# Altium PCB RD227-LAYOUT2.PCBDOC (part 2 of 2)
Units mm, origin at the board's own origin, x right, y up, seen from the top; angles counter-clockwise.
Board outline 90 x 40 mm, 4 copper layers (TOP, Mid-Layer 1, Mid-Layer 2, BOTTOM), stack 0.711 mm thick; 157 components, 70 nets, 404 pads, 437 vias.
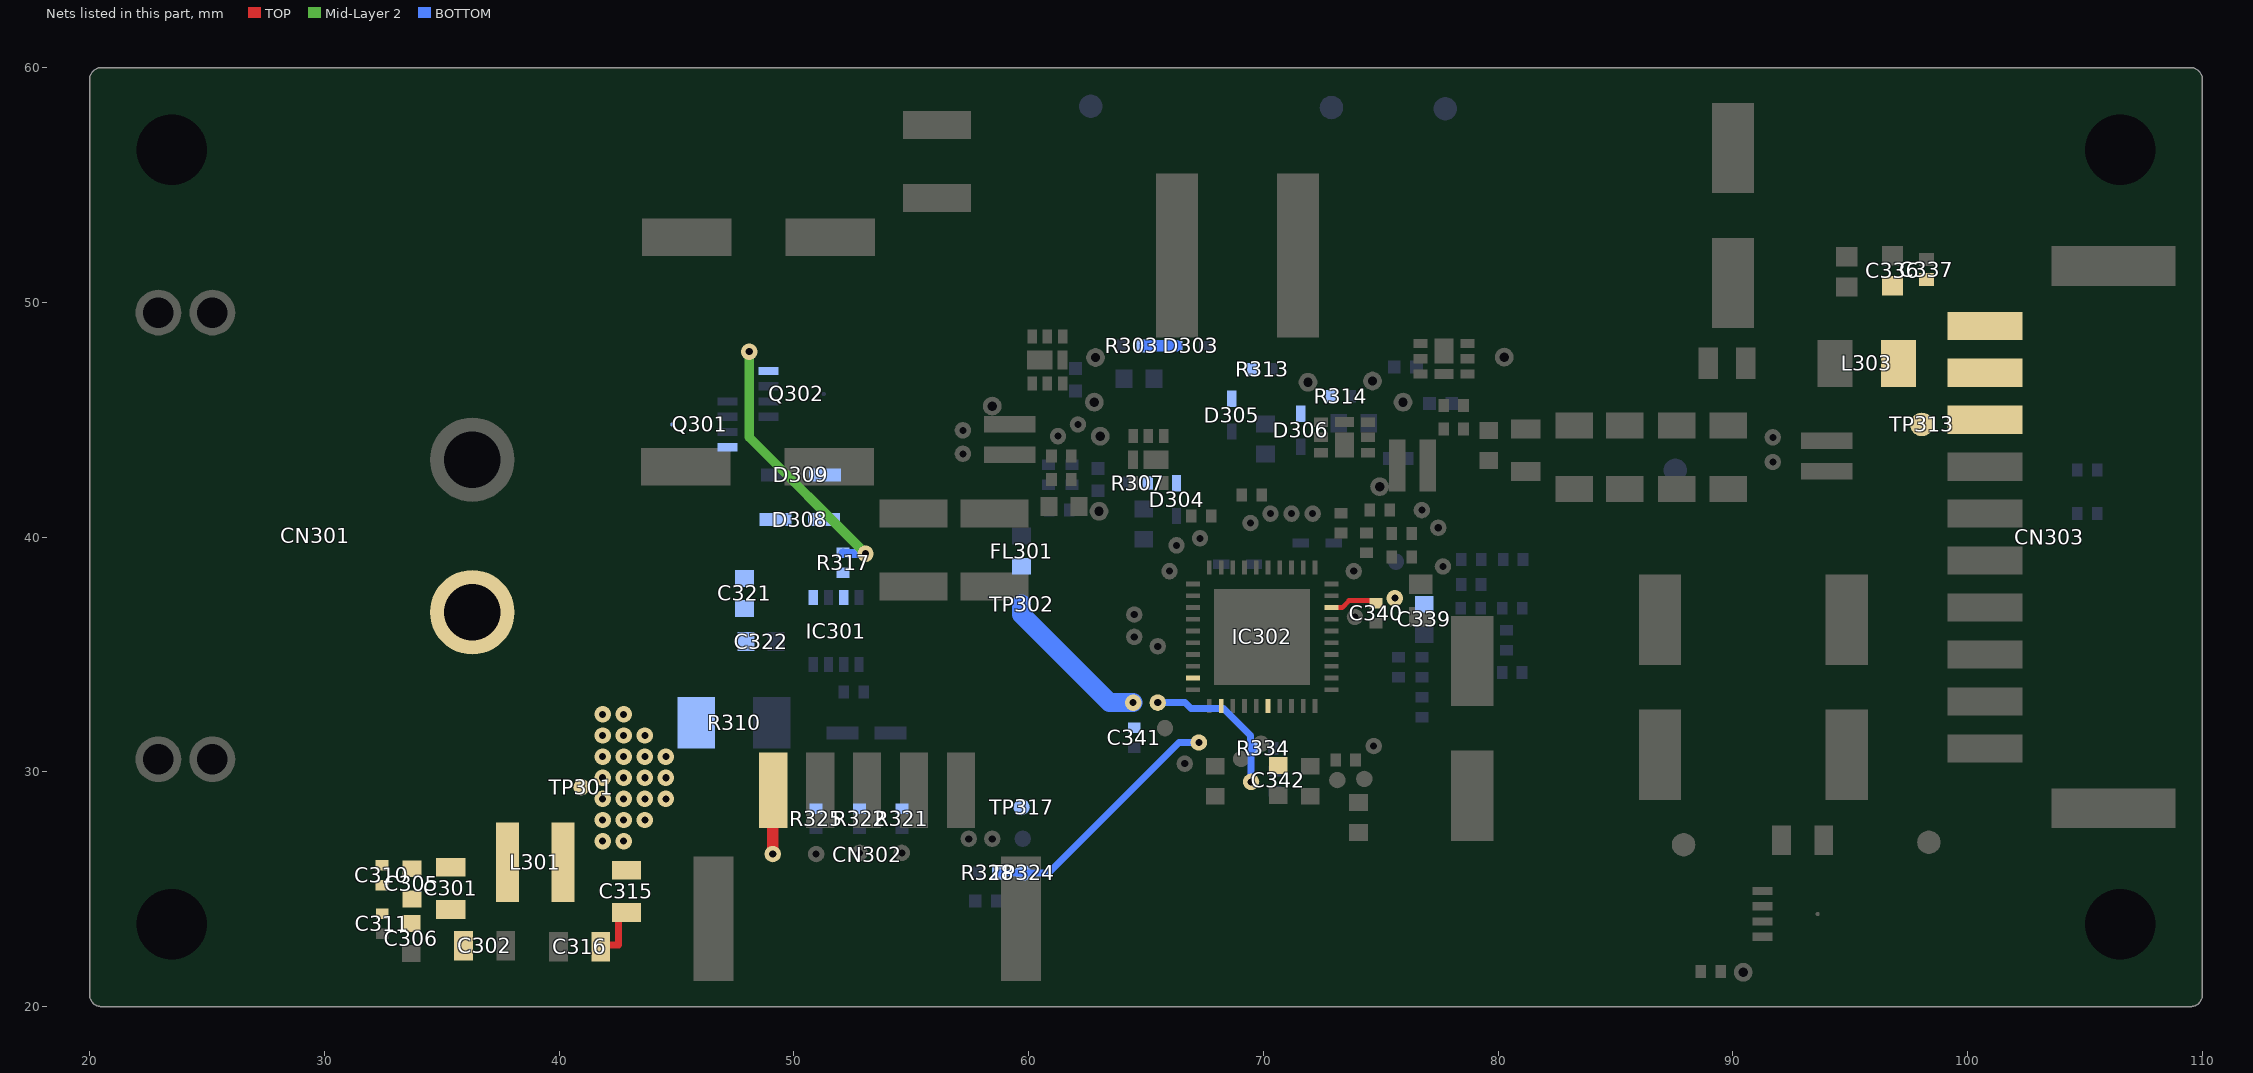
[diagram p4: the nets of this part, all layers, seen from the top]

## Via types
v1: diameter 0.7, hole 0.3, TOP to BOTTOM, 412 vias
v2: diameter 0.8, hole 0.4, TOP to BOTTOM, 25 vias

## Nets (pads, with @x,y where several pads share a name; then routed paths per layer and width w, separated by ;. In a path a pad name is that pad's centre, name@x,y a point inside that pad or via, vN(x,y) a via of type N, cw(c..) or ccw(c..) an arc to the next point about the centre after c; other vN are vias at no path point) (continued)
SIG370: IC302.12 pad.@67.25,31.25 R328.1 TP324.1 | length 10.9
  BOTTOM w0.3: R328.1@58.675,25.7 TP324.1@59.75,25.7 60.85,25.7 66.4,31.25 pad.@67.25,31.25
SIG377: D303.A R303.2 | length 1.3
  BOTTOM w0.5: R303.2@64.975,48.15 D303.A@66.3,48.15
SIG378: D304.A R307.2
SIG395: C301.1 C302.2
SIG396: C305.1 C306.2
SIG397: C310.1 C311.2
SIG401: IC301.3 R317.1
SIG402: C321.1 C322.2
SIG406: D305.A R313.2
SIG411: C315.1 C316.2 | length 2.1
  TOP w0.3: C316.2@41.802,22.63 42.531,22.63 C315.1@42.531,23.955
SIG423: D306.A R314.2
SIG431: D308.A Q301.4 Q302.4 R317.2 | length 11.6
  Mid-Layer 2 w0.4: v1(48.1,47.9) 48.1,44.25 v1(53.05,39.3)
  BOTTOM w0.4: R317.2@52.1,39.325 52.125,39.3 v1(53.05,39.3) v1@53.075,39.3
SIG434: D308.C D309.C
VBAT: C339.2 C340.2 FL301.2 IC302.28 TP302.1 | length 9
  TOP w0.2: IC302.28@72.898,37 73.35,37 73.65,37.3 C340.2@74.925,37.3
  BOTTOM w0.3: v1(75.6,37.4) v1@75.646,37.446
  BOTTOM w0.8: TP302.1@59.7,37.15 59.7,36.7 63.45,32.95 v1(64.45,32.95)
VBUS: C336.2 C337.2 CN303.8 CN303.9 CN303.10 L303.2 TP313.1
VDD: C341.2 C342.1 CN302.1 IC302.9 IC302.16 pad.@49.1,26.5 pad.@65.5,32.95 pad.@69.475,29.575 R321.1 R322.1 R325.1 R334.1 TP317.1 | length 9.3
  TOP w0.5: pad.@49.1,26.5 CN302.1@49.1,29.2
  BOTTOM w0.3: pad.@65.5,32.95 66.664,32.95 66.914,32.7 68.3,32.7 69.45,31.55 69.45,31.125 R334.1@69.575,31 69.475,30.9 pad.@69.475,29.575
VIN: C301.2 C305.2 C310.2 CN301.1 L301.1
VIN2: C315.2 C321.2 IC301.1 L301.2 Q301.5 R310.2 TP301.1
  other v1: 41.85,27.05 42.75,27.05 41.85,27.95 42.75,27.95 43.65,27.95 41.85,28.85 42.75,28.85 43.65,28.85 44.55,28.85 41.85,29.75 42.75,29.75 43.65,29.75 44.55,29.75 41.85,30.65 42.75,30.65 43.65,30.65 44.55,30.65 41.85,31.55 42.75,31.55 43.65,31.55 41.85,32.45 42.75,32.45
pads on no net: CAM10. CAM11. CAM12. CAM13. IC301.4 IC301.7 IC301.8

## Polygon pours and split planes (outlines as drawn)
DH1 on TOP "TOP1" (solid, pour order 73): 67.65,38.4 cw(c67.65,38.45) 67.6,38.45 67.6,39.2 66.965,39.835 cw(c67,39.871) 66.95,39.871 66.95,40.079 cw(c67,40.079) 66.965,40.115 67.135,40.285 cw(c67.171,40.25) 67.171,40.3 67.429,40.3 cw(c67.429,40.25) 67.465,40.285 67.785,39.965 cw(c67.75,39.929) 67.8,39.929 67.8,38.45 cw(c67.75,38.45) 67.75,38.4
SIG319 on TOP "TOP2" (solid, pour order 74): 75.271,39.85 cw(c75.271,39.9) 75.235,39.865 75.15,39.95 73.1,39.95 cw(c73.1,40) 73.05,40 73.05,40.35 cw(c73.1,40.35) 73.1,40.4 75.55,40.4 cw(c75.55,40.35) 75.6,40.35 75.6,39.9 cw(c75.55,39.9) 75.55,39.85
CSP2 on TOP "TOP3" (solid, pour order 75): 75.3,40.9 cw(c75.3,40.95) 75.25,40.95 75.25,41.35 cw(c75.3,41.35) 75.3,41.4 75.65,41.4 75.885,41.635 cw(c75.921,41.6) 75.921,41.65 76.05,41.65 cw(c76.05,41.6) 76.1,41.6 76.1,41.371 cw(c76.05,41.371) 76.085,41.335 75.665,40.915 cw(c75.629,40.95) 75.629,40.9
OUT on TOP "TOP4" (solid, pour order 76): 76.15,39.95 cw(c76.15,40) 76.1,40 76.1,40.829 cw(c76.15,40.829) 76.115,40.865 76.385,41.135 cw(c76.421,41.1) 76.421,41.15 77,41.15 cw(c77,41.1) 77.05,41.1 77.05,41.021 cw(c77,41.021) 77.035,40.985 76.55,40.5 76.55,40 cw(c76.5,40) 76.5,39.95
SIG318 on TOP "TOP5" (solid, pour order 77): 72.75,37.9 cw(c72.75,37.95) 72.7,37.95 72.7,38.05 cw(c72.75,38.05) 72.75,38.1 73,38.1 73.435,38.535 cw(c73.471,38.5) 73.471,38.55 74,38.55 cw(c74,38.5) 74.05,38.5 74.05,38.25 cw(c74,38.25) 74,38.2 73.5,38.2 73.215,37.915 cw(c73.179,37.95) 73.179,37.9
SIG310 on TOP "TOP6" (solid, pour order 78): 73.15,36.4 cw(c73.15,36.45) 73.1,36.45 73.1,36.55 cw(c73.15,36.55) 73.15,36.6 73.4,36.6 73.685,36.885 cw(c73.721,36.85) 73.721,36.9 73.9,36.9 cw(c73.9,36.85) 73.95,36.85 73.95,36.45 cw(c73.9,36.45) 73.9,36.4
SIG324 on TOP "TOP7" (solid, pour order 79): 75.071,38.9 cw(c75.071,38.95) 75.035,38.915 74.85,39.1 74.2,39.1 cw(c74.2,39.15) 74.15,39.15 74.15,39.5 cw(c74.2,39.5) 74.2,39.55 75.079,39.55 cw(c75.079,39.5) 75.115,39.535 75.25,39.4 75.45,39.4 cw(c75.45,39.35) 75.5,39.35 75.5,38.95 cw(c75.45,38.95) 75.45,38.9
SIG328 on TOP "TOP8" (solid, pour order 80): 73,40.8 cw(c73,40.85) 72.95,40.85 72.95,41.2 cw(c73,41.2) 73,41.25 73.7,41.25 73.835,41.385 cw(c73.871,41.35) 73.871,41.4 74.6,41.4 cw(c74.6,41.35) 74.65,41.35 74.65,40.95 cw(c74.6,40.95) 74.6,40.9 74.2,40.9 74.115,40.815 cw(c74.079,40.85) 74.079,40.8
CSN2 on TOP "TOP9" (solid, pour order 81): 76.15,38.9 cw(c76.15,38.95) 76.1,38.95 76.1,39.4 cw(c76.15,39.4) 76.15,39.45 76.65,39.45 77.1,39.9 77.1,40.45 cw(c77.15,40.45) 77.15,40.5 77.75,40.5 cw(c77.75,40.45) 77.8,40.45 77.8,40.021 cw(c77.75,40.021) 77.785,39.985 76.715,38.915 cw(c76.679,38.95) 76.679,38.9
BIAS on TOP "TOP10" (solid, pour order 82): 20 vertices, not listed, extent 74.55,37.6 78,38.85
VBAT on TOP "TOP11" (solid, pour order 83): 74.621,36.95 cw(c74.621,37) 74.585,36.965 74.365,37.185 cw(c74.4,37.221) 74.35,37.221 74.35,37.35 cw(c74.4,37.35) 74.4,37.4 75.15,37.4 75.235,37.485 cw(c75.271,37.45) 75.271,37.5 75.85,37.5 cw(c75.85,37.45) 75.9,37.45 75.9,37.071 cw(c75.85,37.071) 75.885,37.035 75.815,36.965 cw(c75.779,37) 75.779,36.95
DH2 on TOP "TOP12" (solid, pour order 84): 69.15,38.45 cw(c69.15,38.5) 69.1,38.5 69.1,40.579 cw(c69.15,40.579) 69.115,40.615 69.235,40.735 cw(c69.271,40.7) 69.271,40.75 69.629,40.75 cw(c69.629,40.7) 69.665,40.735 69.785,40.615 cw(c69.75,40.579) 69.8,40.579 69.8,40.371 cw(c69.75,40.371) 69.785,40.335 69.3,39.85 69.3,38.5 cw(c69.25,38.5) 69.25,38.45
DL2 on TOP "TOP13" (solid, pour order 85): 70.15,38.4 cw(c70.15,38.45) 70.1,38.45 70.1,39.529 cw(c70.15,39.529) 70.115,39.565 70.85,40.3 70.85,40.95 cw(c70.9,40.95) 70.9,41 71.5,41 cw(c71.5,40.95) 71.55,40.95 71.55,40.521 cw(c71.5,40.521) 71.535,40.485 70.3,39.25 70.3,38.45 cw(c70.25,38.45) 70.25,38.4
BST1 on TOP "TOP14" (solid, pour order 86): 37 vertices, not listed, extent 65.95,37.9 67.2,40.85
DL1 on TOP "TOP15" (solid, pour order 87): 66.521,37.4 cw(c66.521,37.45) 66.485,37.415 65.665,38.235 cw(c65.7,38.271) 65.65,38.271 65.65,38.5 cw(c65.7,38.5) 65.7,38.55 66.3,38.55 cw(c66.3,38.5) 66.35,38.5 66.35,37.95 66.7,37.6 67.2,37.6 cw(c67.2,37.55) 67.25,37.55 67.25,37.45 cw(c67.2,37.45) 67.2,37.4
SIG337 on TOP "TOP16" (solid, pour order 88): 64.55,36.4 cw(c64.55,36.45) 64.5,36.45 64.5,36.8 cw(c64.55,36.8) 64.55,36.85 64.729,36.85 cw(c64.729,36.8) 64.765,36.835 65,36.6 67.25,36.6 cw(c67.25,36.55) 67.3,36.55 67.3,36.45 cw(c67.25,36.45) 67.25,36.4
SIG335 on TOP "TOP17" (solid, pour order 89): 64.25,35.7 cw(c64.25,35.75) 64.2,35.75 64.2,35.979 cw(c64.25,35.979) 64.215,36.015 64.285,36.085 cw(c64.321,36.05) 64.321,36.1 67.25,36.1 cw(c67.25,36.05) 67.3,36.05 67.3,35.95 cw(c67.25,35.95) 67.25,35.9 65,35.9 64.815,35.715 cw(c64.779,35.75) 64.779,35.7
HVEN on TOP "TOP18" (solid, pour order 90): 65.45,35.05 cw(c65.45,35.1) 65.4,35.1 65.4,35.65 cw(c65.45,35.65) 65.45,35.7 65.779,35.7 cw(c65.779,35.65) 65.815,35.685 65.9,35.6 67.25,35.6 cw(c67.25,35.55) 67.3,35.55 67.3,35.45 cw(c67.25,35.45) 67.25,35.4 66.1,35.4 65.765,35.065 cw(c65.729,35.1) 65.729,35.05
GDRV on TOP "TOP19" (solid, pour order 91): 65.55,33.65 cw(c65.55,33.7) 65.5,33.7 65.5,34.3 cw(c65.55,34.3) 65.55,34.35 66.309,34.35 66.529,34.571 cw(c66.6,34.5) 66.6,34.6 67.002,34.6 cw(c67.002,34.5) 67.002,34.4 66.641,34.4 66.527,34.286 cw(c66.479,34.3) 66.515,34.265 66.514,34.264 65.915,33.665 cw(c65.879,33.7) 65.879,33.65
VDD on TOP "TOP20" (solid, pour order 92): 20 vertices, not listed, extent 65.3,32.6 67.102,34.1
HVCC1 on TOP "TOP21" (solid, pour order 93): 18 vertices, not listed, extent 72.798,34.784 74.8,35.6
HVCC2 on TOP "TOP22" (solid, pour order 94): 74.55,34.1 cw(c74.55,34.2) 74.479,34.129 73.709,34.9 72.898,34.9 cw(c72.898,35) 72.898,35.1 73.75,35.1 cw(c73.75,35) 73.821,35.071 74.342,34.549 cw(c74.35,34.5) 74.35,34.55 74.75,34.55 cw(c74.75,34.5) 74.8,34.5 74.8,34.3 cw(c74.8,34.2) 74.8,34.1
HVDM on TOP "TOP23" (solid, pour order 95): 73.441,32.75 cw(c73.441,32.85) 73.371,32.779 73.329,32.821 cw(c73.4,32.891) 73.3,32.891 73.3,33.259 73.159,33.4 72.898,33.4 cw(c72.898,33.5) 72.898,33.6 73.2,33.6 cw(c73.2,33.5) 73.271,33.571 73.92,32.921 73.921,32.921 cw(c73.85,32.85) 73.95,32.85 cw(c73.85,32.85) 73.85,32.75
HVDP on TOP "TOP24" (solid, pour order 96): 74.45,31.95 cw(c74.45,32.05) 74.35,32.05 74.35,32.959 73.409,33.9 72.898,33.9 cw(c72.898,34) 72.898,34.1 73.45,34.1 cw(c73.45,34) 73.521,34.071 74.827,32.765 cw(c74.756,32.694) 74.856,32.694 74.856,32.452 74.967,32.079 cw(c74.871,32.05) 74.871,31.95
SIG369 on TOP "TOP25" (solid, pour order 97): 19 vertices, not listed, extent 66.311,30.25 67.8,33.152
SIG370 on TOP "TOP26" (solid, pour order 98): 67.129,31.15 cw(c67.129,31.25) 67.029,31.25 67.029,31.409 cw(c67.129,31.409) 67.059,31.479 67.224,31.644 cw(c67.294,31.574) 67.271,31.671 68.1,32.5 68.1,33.052 cw(c68.2,33.052) 68.3,33.052 68.3,32.391 cw(c68.2,32.391) 68.271,32.321 67.6,31.65 67.6,31.25 cw(c67.5,31.25) 67.5,31.15
SIG346 on TOP "TOP27" (solid, pour order 99): 67.65,29.9 cw(c67.65,30) 67.55,30 67.55,30.609 cw(c67.65,30.609) 67.579,30.679 67.85,30.95 67.85,31.388 cw(c68,31.388) 67.894,31.494 68.6,32.2 68.6,33.052 cw(c68.7,33.052) 68.8,33.052 68.8,31.591 cw(c68.7,31.591) 68.771,31.521 68.35,31.1 68.35,30 cw(c68.25,30) 68.25,29.9
SIG349 on TOP "TOP28" (solid, pour order 100): 68.8,30.45 cw(c68.8,30.55) 68.7,30.55 68.7,31.009 cw(c68.8,31.009) 68.729,31.079 69.1,31.45 69.1,33.052 cw(c69.2,33.052) 69.3,33.052 69.3,30.9 69.371,30.829 cw(c69.3,30.759) 69.4,30.759 69.4,30.55 cw(c69.3,30.55) 69.3,30.45
SIG347 on TOP "TOP29" (solid, pour order 101): 71.7,29.9 cw(c71.7,30) 71.6,30 71.6,31.1 70.629,32.071 cw(c70.7,32.141) 70.6,32.141 70.6,33.052 cw(c70.7,33.052) 70.8,33.052 70.8,32.35 72.371,30.779 cw(c72.3,30.709) 72.4,30.709 72.4,30 cw(c72.3,30) 72.3,29.9
ALERT on TOP "TOP30" (solid, pour order 102): 21 vertices, not listed, extent 72.1,31 74.8,32.841
LX1 on TOP "TOP31" (solid, pour order 103): 21 vertices, not listed, extent 67.25,38.4 68.3,43.2
CSP1 on TOP "TOP32" (solid, pour order 104): 60.7,44 cw(c60.7,44.05) 60.65,44.05 60.65,44.179 cw(c60.7,44.179) 60.665,44.215 61.085,44.635 cw(c61.121,44.6) 61.121,44.65 61.25,44.65 cw(c61.25,44.6) 61.3,44.6 61.3,44.05 cw(c61.25,44.05) 61.25,44
CSN1 on TOP "TOP33" (solid, pour order 105): 61.821,44.65 cw(c61.821,44.7) 61.785,44.665 61.515,44.935 cw(c61.55,44.971) 61.5,44.971 61.5,45.05 cw(c61.55,45.05) 61.55,45.1 62.15,45.1 cw(c62.15,45.05) 62.2,45.05 62.2,44.7 cw(c62.15,44.7) 62.15,44.65
GND_A on TOP "TOP34" (solid, pour order 106): 46,21 cw(c46,21.15) 45.85,21.15 45.85,24.65 cw(c46,24.65) 46,24.8 55.45,24.8 56.55,25.9 56.55,30.85 cw(c56.7,30.85) 56.7,31 58.838,31 cw(c58.838,30.85) 58.944,30.956 60.506,29.394 cw(c60.4,29.288) 60.55,29.288 60.55,21.15 cw(c60.4,21.15) 60.4,21
VIN on TOP "TOP35" (solid, pour order 107): 41 vertices, not listed, extent 32.144,24.463 38.304,38.65
OUT on TOP "TOP36" (solid, pour order 108): 49 vertices, not listed, extent 76.694,32.75 96.1,45.85
SIG341 on TOP "TOP37" (solid, pour order 109): 24 vertices, not listed, extent 65.65,31.75 67.102,33.6
VIN2 on TOP "TOP38" (solid, pour order 110): 26 vertices, not listed, extent 39.666,24.507 44.9,33.454
SIG395 on TOP "TOP39" (solid, pour order 111): 35.6,22 cw(c35.6,22.05) 35.55,22.05 35.55,22.4 34.815,23.135 cw(c34.85,23.171) 34.8,23.171 34.8,24.1 cw(c34.85,24.1) 34.85,24.15 35.95,24.15 cw(c35.95,24.1) 36,24.1 36,23.65 36.285,23.365 cw(c36.25,23.329) 36.3,23.329 36.3,22.05 cw(c36.25,22.05) 36.25,22
SIG396 on TOP "TOP40" (solid, pour order 112): 33.35,23.45 cw(c33.35,23.5) 33.3,23.5 33.3,24.55 cw(c33.35,24.55) 33.35,24.6 34.05,24.6 cw(c34.05,24.55) 34.1,24.55 34.1,23.5 cw(c34.05,23.5) 34.05,23.45
SIG397 on TOP "TOP41" (solid, pour order 113): 32.25,23.85 cw(c32.25,23.9) 32.2,23.9 32.2,25.2 cw(c32.25,25.2) 32.25,25.25 32.65,25.25 cw(c32.65,25.2) 32.7,25.2 32.7,23.9 cw(c32.65,23.9) 32.65,23.85
GND_A on TOP "TOP42" (solid, pour order 114): 108.05,37.1 cw(c108.05,37.15) 108,37.15 108,43.8 cw(c108.05,43.8) 108.05,43.85 108.95,43.85 cw(c108.95,43.8) 109,43.8 109,37.15 cw(c108.95,37.15) 108.95,37.1
SIG350 on TOP "TOP43" (solid, pour order 115): 69.65,31.2 cw(c69.65,31.3) 69.55,31.3 69.55,31.409 cw(c69.65,31.409) 69.579,31.479 69.6,31.5 69.6,33.052 cw(c69.7,33.052) 69.8,33.052 69.8,31.8 70.146,31.454 cw(c70.075,31.383) 70.175,31.383 70.175,31.316 cw(c70.075,31.316) 70.146,31.245 70.13,31.229 cw(c70.06,31.3) 70.06,31.2
BST2 on TOP "TOP44" (solid, pour order 116): 24 vertices, not listed, extent 69.6,38.8 70.65,41.95
ADDR on TOP "TOP45" (solid, pour order 117): 70.6,39.2 cw(c70.7,39.2) 70.629,39.271 71.754,40.396 71.754,40.914 cw(c71.854,40.914) 71.854,41.014 72.327,41.014 cw(c72.327,40.914) 72.427,40.914 72.427,40.869 cw(c72.327,40.869) 72.398,40.798 72.2,40.6 cw(c72.1,40.6) 72.171,40.529 70.8,39.159 70.8,38.948 cw(c70.7,38.948) 70.6,38.948
CSP1 on TOP "TOP46" (solid, pour order 118): 23 vertices, not listed, extent 49.65,40.402 61.2,55.1
GDRV on TOP "TOP47" (solid, pour order 119): 89.3,21.1 cw(c89.3,21.15) 89.25,21.15 89.25,21.75 cw(c89.3,21.75) 89.3,21.8 90.2,21.8 90.837,22.437 90.837,23.05 cw(c90.887,23.05) 90.887,23.1 91.65,23.1 cw(c91.65,23.05) 91.7,23.05 91.7,21.721 cw(c91.65,21.721) 91.685,21.685 91.115,21.115 cw(c91.079,21.15) 91.079,21.1
SIG345 on TOP "TOP48" (solid, pour order 120): 20 vertices, not listed, extent 71.1,29.65 73.5,33.152
SIG344 on TOP "TOP49" (solid, pour order 121): 27 vertices, not listed, extent 71.6,29.7 74.55,33.152
GND_A on TOP "TOP50" (solid, pour order 122): 77 vertices, not listed, extent 67.55,28.337 77.188,37
LX2 on TOP "TOP51" (solid, pour order 123): 19 vertices, not listed, extent 68.6,38.4 69.525,43.186
DH2_Q on TOP "TOP52" (solid, pour order 124): 74.2,44.7 cw(c74.2,44.75) 74.15,44.75 74.15,45.929 cw(c74.2,45.929) 74.165,45.965 74.3,46.1 74.3,46.65 cw(c74.35,46.65) 74.35,46.7 74.9,46.7 cw(c74.9,46.65) 74.95,46.65 74.95,44.75 cw(c74.9,44.75) 74.9,44.7
DL2_Q on TOP "TOP53" (solid, pour order 125): 75.65,45.7 cw(c75.65,45.75) 75.6,45.75 75.6,47.1 cw(c75.65,47.1) 75.65,47.15 76.65,47.15 cw(c76.65,47.1) 76.7,47.1 76.7,46.771 cw(c76.65,46.771) 76.685,46.735 76.4,46.45 76.4,45.871 cw(c76.35,45.871) 76.385,45.835 76.265,45.715 cw(c76.229,45.75) 76.229,45.7
CSP2 on TOP "TOP54" (solid, pour order 126): 30 vertices, not listed, extent 71.55,41.75 76.107,44.45
GND_P on TOP "TOP55" (solid, pour order 127): 46 vertices, not listed, extent 77.3,44.2 99.05,59
DH1_Q on TOP "TOP56" (solid, pour order 128): 62.571,45.4 cw(c62.571,45.45) 62.535,45.415 61.75,46.2 61.3,46.2 cw(c61.3,46.25) 61.25,46.25 61.25,46.8 cw(c61.3,46.8) 61.3,46.85 62.079,46.85 cw(c62.079,46.8) 62.115,46.835 62.935,46.015 cw(c62.9,45.979) 62.95,45.979 62.95,45.45 cw(c62.9,45.45) 62.9,45.4
GND_P on TOP "TOP57" (solid, pour order 129): 226 vertices, not listed, extent 21.05,21 95.65,58.93
DL1_Q on TOP "TOP58" (solid, pour order 130): 62.871,44 cw(c62.871,44.05) 62.835,44.015 62.765,44.085 cw(c62.8,44.121) 62.75,44.121 62.75,44.479 cw(c62.8,44.479) 62.765,44.515 62.835,44.585 cw(c62.871,44.55) 62.871,44.6 64.6,44.6 cw(c64.6,44.55) 64.65,44.55 64.65,44.05 cw(c64.6,44.05) 64.6,44
CSN1 on TOP "TOP59" (solid, pour order 131): 28 vertices, not listed, extent 58.05,44.6 61,49.05
SHLD_SNS on TOP "TOP60" (solid, pour order 132): 54 vertices, not listed, extent 92.14,20.987 108.927,52.721
VBUS on TOP "TOP61" (solid, pour order 133): 20 vertices, not listed, extent 96.35,44.221 102.3,51
CSN2 on TOP "TOP62" (solid, pour order 134): 21 vertices, not listed, extent 89.1,43.8 95.3,52.7
VDD on TOP "TOP63" (solid, pour order 135): 24 vertices, not listed, extent 69.273,29.373 71,33.152
LX1 on TOP "TOP64" (solid, pour order 136): 46 vertices, not listed, extent 61.25,42.1 67.3,56.45
LX2 on TOP "TOP65" (solid, pour order 137): 49 vertices, not listed, extent 70.6,44.699 79.05,56.35
SHLD_SNS on Mid-Layer 1 "MID166" (solid, pour order 61): 92.295,22.65 cw(c92.295,22.75) 92.195,22.75 92.195,24.668 cw(c92.295,24.668) 92.295,24.768 94.144,24.768 cw(c94.144,24.668) 94.244,24.668 94.244,22.75 cw(c94.144,22.75) 94.144,22.65
CSP1 on Mid-Layer 1 "MID168" (solid, pour order 63): 54.271,44.15 cw(c54.271,44.2) 54.235,44.165 53.165,45.235 cw(c53.2,45.271) 53.15,45.271 53.15,50.35 cw(c53.2,50.35) 53.2,50.4 57.4,50.4 cw(c57.4,50.35) 57.45,50.35 57.45,46.171 cw(c57.4,46.171) 57.435,46.135 55.465,44.165 cw(c55.429,44.2) 55.429,44.15
VBAT on Mid-Layer 1 "MID169" (solid, pour order 64): 28 vertices, not listed, extent 64.05,31.855 75.879,37.523
SHLD_SNS on Mid-Layer 1 "MID170" (solid, pour order 65): 18 vertices, not listed, extent 92.2,20.987 106.598,33.739
CSN1 on Mid-Layer 1 "MID171" (solid, pour order 66): 59.571,45.5 cw(c59.571,45.55) 59.535,45.515 58.915,46.135 cw(c58.95,46.171) 58.9,46.171 58.9,48.95 cw(c59.05,48.95) 59.05,49.1 60.9,49.1 cw(c60.9,48.95) 61.05,48.95 61.05,45.65 cw(c60.9,45.65) 60.9,45.5
LX1 on Mid-Layer 1 "MID172" (solid, pour order 67): 67,42.8 cw(c67,42.85) 66.95,42.85 66.95,42.979 cw(c67,42.979) 66.965,43.015 67.185,43.235 cw(c67.221,43.2) 67.221,43.25 67.6,43.25 cw(c67.6,43.2) 67.65,43.2 67.65,42.85 cw(c67.6,42.85) 67.6,42.8
LX1 on Mid-Layer 1 "MID173" (solid, pour order 68): 63.8,42.65 cw(c63.8,42.8) 63.65,42.8 63.65,46.1 cw(c63.7,46.1) 63.7,46.15 65.829,46.15 cw(c65.829,46.1) 65.865,46.135 66.785,45.215 cw(c66.75,45.179) 66.8,45.179 66.8,43.171 cw(c66.75,43.171) 66.785,43.135 66.315,42.665 cw(c66.279,42.7) 66.279,42.65
CSP2 on Mid-Layer 1 "MID174" (solid, pour order 69): 71.9,41.75 cw(c71.9,41.9) 71.75,41.9 71.75,43.9 cw(c71.9,43.9) 71.9,44.05 75.25,44.05 cw(c75.25,43.9) 75.4,43.9 75.4,41.9 cw(c75.25,41.9) 75.25,41.75
LX2 on Mid-Layer 1 "MID175" (solid, pour order 70): 75.85,46.95 cw(c75.85,47.1) 75.7,47.1 75.7,49.422 cw(c75.85,49.422) 75.85,49.572 78.9,49.572 cw(c78.9,49.422) 79.05,49.422 79.05,47.371 cw(c79,47.371) 79.035,47.335 78.665,46.965 cw(c78.629,47) 78.629,46.95
GND_A on Mid-Layer 1 "MID177" (solid, pour order 72): 29 vertices, not listed, extent 68.35,28.424 108.95,44.863
VIN2 on Mid-Layer 1 "MID167" (solid, pour order 62): 41.5,26.65 cw(c41.5,26.7) 41.45,26.7 41.45,32.85 cw(c41.5,32.85) 41.5,32.9 43.129,32.9 cw(c43.129,32.85) 43.165,32.885 44.935,31.115 cw(c44.9,31.079) 44.95,31.079 44.95,28.321 cw(c44.9,28.321) 44.935,28.285 43.315,26.665 cw(c43.279,26.7) 43.279,26.65
GND_P on Mid-Layer 1 "MID176" (solid, pour order 71): 142 vertices, not listed, extent 20.986,21 101.75,58.981
GND_A on Mid-Layer 2 "MID288" (solid, pour order 60): 40 vertices, not listed, extent 68.35,28.2 108.9,44.863
GND_P on Mid-Layer 2 "MID278" (solid, pour order 50): 68.094,33.7 cw(c68.094,33.85) 67.944,33.85 67.944,37.65 cw(c68.094,37.65) 68.094,37.8 71.852,37.8 cw(c71.852,37.65) 72.002,37.65 72.002,33.85 cw(c71.852,33.85) 71.852,33.7
GND_P on Mid-Layer 2 "MID281" (solid, pour order 53): 17 vertices, not listed, extent 79.9,28.2 93.7,29.45
SHLD_SNS on Mid-Layer 2 "MID282" (solid, pour order 54): 18 vertices, not listed, extent 92.2,20.987 106.692,33.954
LX1 on Mid-Layer 2 "MID283" (solid, pour order 55): 64.05,42.9 cw(c64.05,43.05) 63.9,43.05 63.9,46.05 cw(c63.95,46.05) 63.95,46.1 65.879,46.1 cw(c65.879,46.05) 65.915,46.085 66.785,45.215 cw(c66.75,45.179) 66.8,45.179 66.8,43.05 cw(c66.65,43.05) 66.65,42.9
CSP2 on Mid-Layer 2 "MID285" (solid, pour order 57): 71.75,41.75 cw(c71.75,41.9) 71.6,41.9 71.6,43.75 cw(c71.75,43.75) 71.75,43.9 72.8,43.9 73.085,44.185 cw(c73.121,44.15) 73.121,44.2 74.179,44.2 cw(c74.179,44.15) 74.215,44.185 75.385,43.015 cw(c75.35,42.979) 75.4,42.979 75.4,41.8 cw(c75.35,41.8) 75.35,41.75
VIN2 on Mid-Layer 2 "MID279" (solid, pour order 51): 41.5,26.65 cw(c41.5,26.7) 41.45,26.7 41.45,32.85 cw(c41.5,32.85) 41.5,32.9 43.129,32.9 cw(c43.129,32.85) 43.165,32.885 44.935,31.115 cw(c44.9,31.079) 44.95,31.079 44.95,28.321 cw(c44.9,28.321) 44.935,28.285 43.315,26.665 cw(c43.279,26.7) 43.279,26.65
CSP1 on Mid-Layer 2 "MID280" (solid, pour order 52): 54.271,44.15 cw(c54.271,44.2) 54.235,44.165 53.165,45.235 cw(c53.2,45.271) 53.15,45.271 53.15,50.35 cw(c53.2,50.35) 53.2,50.4 57.4,50.4 cw(c57.4,50.35) 57.45,50.35 57.45,46.171 cw(c57.4,46.171) 57.435,46.135 55.465,44.165 cw(c55.429,44.2) 55.429,44.15
CSN1 on Mid-Layer 2 "MID284" (solid, pour order 56): 59.571,45.5 cw(c59.571,45.55) 59.535,45.515 58.915,46.135 cw(c58.95,46.171) 58.9,46.171 58.9,48.9 cw(c59.05,48.9) 59.05,49.05 60.9,49.05 cw(c60.9,48.9) 61.05,48.9 61.05,46.4 cw(c60.9,46.4) 61.039,46.343 cw(c60.992,46.362) 61.028,46.327 60.957,46.256 cw(c60.922,46.291) 60.95,46.25 60.215,45.515 cw(c60.179,45.55) 60.179,45.5
LX2 on Mid-Layer 2 "MID286" (solid, pour order 58): 75.85,46.95 cw(c75.85,47.1) 75.7,47.1 75.7,49.422 cw(c75.85,49.422) 75.85,49.572 78.9,49.572 cw(c78.9,49.422) 79.05,49.422 79.05,47.1 cw(c78.9,47.1) 78.9,46.95
GND_P on Mid-Layer 2 "MID287" (solid, pour order 59): 184 vertices, not listed, extent 20.95,21.05 101.9,59
VBAT on BOTTOM "BOTTOM89" (solid, pour order 2): 76.271,36.8 cw(c76.271,36.85) 76.235,36.815 75.95,37.1 75.6,37.1 cw(c75.6,37.15) 75.55,37.15 75.55,37.7 cw(c75.6,37.7) 75.6,37.75 76.329,37.75 cw(c76.329,37.7) 76.365,37.735 76.6,37.5 77.05,37.5 cw(c77.05,37.45) 77.1,37.45 77.1,36.85 cw(c77.05,36.85) 77.05,36.8
BST1 on BOTTOM "BOTTOM90" (solid, pour order 3): 17 vertices, not listed, extent 66.3,38.65 68.25,39.9
SIG406 on BOTTOM "BOTTOM91" (solid, pour order 4): 68.856,46.091 cw(c68.856,46.341) 68.68,46.518 68.933,46.771 cw(c69.109,46.594) 69.109,46.844 cw(c69.109,46.594) 69.286,46.417 69.033,46.164 cw(c68.856,46.341) 68.856,46.091
DH2 on BOTTOM "BOTTOM92" (solid, pour order 5): 23 vertices, not listed, extent 68.55,40.5 70.477,44.745
BST2 on BOTTOM "BOTTOM93" (solid, pour order 6): 18 vertices, not listed, extent 69.95,39.55 71.85,41
OUT on BOTTOM "BOTTOM94" (solid, pour order 7): 76.771,40.8 cw(c76.771,40.85) 76.735,40.815 76.715,40.835 cw(c76.75,40.871) 76.7,40.871 76.7,41.45 cw(c76.75,41.45) 76.75,41.5 77.029,41.5 cw(c77.029,41.45) 77.065,41.485 77.1,41.45 77.2,41.45 cw(c77.2,41.4) 77.25,41.4 77.25,41.221 cw(c77.2,41.221) 77.235,41.185 76.865,40.815 cw(c76.829,40.85) 76.829,40.8
ADDR on BOTTOM "BOTTOM95" (solid, pour order 8): 40 vertices, not listed, extent 72.008,39.4 79.328,41.342
ADDR on BOTTOM "BOTTOM96" (solid, pour order 9): 79.2,38.8 cw(c79.2,38.95) 79.05,38.95 79.05,39.472 cw(c79.194,39.516) 79.322,39.593 79.615,39.3 80.3,39.3 cw(c80.3,39.15) 80.45,39.15 80.45,38.95 cw(c80.3,38.95) 80.3,38.8
SIG317 on BOTTOM "BOTTOM97" (solid, pour order 10): 22 vertices, not listed, extent 78.964,34.95 80.454,36.25
GND_P on BOTTOM "BOTTOM98" (solid, pour order 11): 68.094,33.7 cw(c68.094,33.85) 67.944,33.85 67.944,37.65 cw(c68.094,37.65) 68.094,37.8 71.852,37.8 cw(c71.852,37.65) 72.002,37.65 72.002,33.85 cw(c71.852,33.85) 71.852,33.7
GND_A on BOTTOM "BOTTOM99" (solid, pour order 12): 53 vertices, not listed, extent 72.15,28.25 82.65,39.318
GND_P on BOTTOM "BOTTOM100" (solid, pour order 13): 48.242,21 cw(c48.242,21.15) 48.092,21.15 48.092,22.15 cw(c48.242,22.15) 48.242,22.3 64.6,22.3 cw(c64.6,22.15) 64.75,22.15 64.75,21.15 cw(c64.6,21.15) 64.6,21
SIG402 on BOTTOM "BOTTOM101" (solid, pour order 14): 47.65,35.15 cw(c47.65,35.2) 47.6,35.2 47.6,36.2 47.515,36.285 cw(c47.55,36.321) 47.5,36.321 47.5,36.9 cw(c47.55,36.9) 47.55,36.95 48.25,36.95 cw(c48.25,36.9) 48.3,36.9 48.3,35.2 cw(c48.25,35.2) 48.25,35.15
SIG247 on BOTTOM "BOTTOM102" (solid, pour order 15): 22 vertices, not listed, extent 48.95,31 52.75,34.65
GND_A on BOTTOM "BOTTOM103" (solid, pour order 16): 29 vertices, not listed, extent 105.526,36.396 108.9,44.272
CSP1 on BOTTOM "BOTTOM104" (solid, pour order 17): 59.7,39.74 cw(c59.7,40.14) 59.3,40.14 59.3,40.884 56.917,43.267 cw(c57.2,43.55) 57.483,43.833 59.983,41.333 cw(c59.7,41.05) 60.1,41.05 60.1,40.14 cw(c59.7,40.14) 59.7,39.74
VBAT on BOTTOM "BOTTOM105" (solid, pour order 18): 59.3,38.62 cw(c59.7,38.62) 59.7,39.02 cw(c59.7,38.62) 60.1,38.62 60.1,37.15 cw(c59.7,37.15) 59.3,37.15
SIG406 on BOTTOM "BOTTOM106" (solid, pour order 19): 68.5,45.6 cw(c68.5,45.65) 68.45,45.65 68.45,46.529 cw(c68.5,46.529) 68.465,46.565 69.285,47.385 cw(c69.321,47.35) 69.321,47.4 69.7,47.4 cw(c69.7,47.35) 69.75,47.35 69.75,46.921 cw(c69.7,46.921) 69.735,46.885 68.85,46 68.85,45.65 cw(c68.8,45.65) 68.8,45.6
DL2_Q on BOTTOM "BOTTOM107" (solid, pour order 20): 22 vertices, not listed, extent 73.5,44.45 77.1,46.25
DH2_Q on BOTTOM "BOTTOM108" (solid, pour order 21): 35 vertices, not listed, extent 69.65,44.448 75.55,47.8
SIG423 on BOTTOM "BOTTOM109" (solid, pour order 22): 71.45,44.9 cw(c71.45,44.95) 71.4,44.95 71.4,45.55 cw(c71.45,45.55) 71.45,45.6 71.9,45.6 72.535,46.235 cw(c72.571,46.2) 72.571,46.25 73,46.25 cw(c73,46.2) 73.05,46.2 73.05,45.8 cw(c73,45.8) 73,45.75 72.7,45.75 71.865,44.915 cw(c71.829,44.95) 71.829,44.9
DL1 on BOTTOM "BOTTOM110" (solid, pour order 23): 20 vertices, not listed, extent 64.5,38.2 66.5,41.15
DL1_Q on BOTTOM "BOTTOM111" (solid, pour order 24): 24 vertices, not listed, extent 62.7,40.9 65.3,44.35
GND_P on BOTTOM "BOTTOM112" (solid, pour order 25): 24 vertices, not listed, extent 62.4,33.7 68.85,42
SIG378 on BOTTOM "BOTTOM113" (solid, pour order 26): 65,42.05 cw(c65,42.1) 64.95,42.1 64.95,42.5 cw(c65,42.5) 65,42.55 66.3,42.55 cw(c66.3,42.5) 66.35,42.5 66.35,42.1 cw(c66.3,42.1) 66.3,42.05
LX1 on BOTTOM "BOTTOM114" (solid, pour order 27): 61.95,46.9 cw(c61.95,46.95) 61.9,46.95 61.9,47.429 cw(c61.95,47.429) 61.915,47.465 62.435,47.985 cw(c62.471,47.95) 62.471,48 62.9,48 cw(c62.9,47.95) 62.95,47.95 62.95,47.35 cw(c62.9,47.35) 62.9,47.3 62.75,47.3 62.365,46.915 cw(c62.329,46.95) 62.329,46.9
DH1 on BOTTOM "BOTTOM115" (solid, pour order 28): 67.371,45.75 cw(c67.371,45.8) 67.335,45.765 66.815,46.285 cw(c66.85,46.321) 66.8,46.321 66.8,46.5 cw(c66.85,46.5) 66.85,46.55 67.45,46.55 cw(c67.45,46.5) 67.5,46.5 67.5,45.8 cw(c67.45,45.8) 67.45,45.75
GND_P on BOTTOM "BOTTOM116" (solid, pour order 29): 151 vertices, not listed, extent 20.95,21 102.5,58.95
SHLD_SNS on BOTTOM "BOTTOM117" (solid, pour order 30): 18 vertices, not listed, extent 92.2,20.987 106.682,33.886
BIAS on BOTTOM "BOTTOM118" (solid, pour order 31): 34 vertices, not listed, extent 69.423,38.4 78.6,39.95
GND_A on BOTTOM "BOTTOM119" (solid, pour order 32): 36 vertices, not listed, extent 56.8,26.75 70.8,32.25
GND_P on BOTTOM "BOTTOM120" (solid, pour order 33): 29 vertices, not listed, extent 49,31.2 58.45,38.2
LX2 on BOTTOM "BOTTOM121" (solid, pour order 34): 76.4,46.95 cw(c76.4,47.1) 76.25,47.1 76.25,48.05 75.715,48.585 cw(c75.75,48.621) 75.7,48.621 75.7,49.129 cw(c75.75,49.129) 75.715,49.165 76.107,49.557 cw(c76.142,49.522) 76.142,49.572 78.9,49.572 cw(c78.9,49.422) 79.05,49.422 79.05,47.421 cw(c79,47.421) 79.035,47.385 78.615,46.965 cw(c78.579,47) 78.579,46.95
DL2 on BOTTOM "BOTTOM122" (solid, pour order 35): 22 vertices, not listed, extent 70.85,41 73.3,45.25
CSP2 on BOTTOM "BOTTOM123" (solid, pour order 36): 72.55,41.75 cw(c72.55,41.9) 72.4,41.9 72.4,43.379 cw(c72.45,43.379) 72.415,43.415 73.035,44.035 cw(c73.071,44) 73.071,44.05 75.35,44.05 cw(c75.35,43.9) 75.5,43.9 75.5,41.9 cw(c75.35,41.9) 75.35,41.75
LX1 on BOTTOM "BOTTOM124" (solid, pour order 37): 17 vertices, not listed, extent 64.45,42.9 66.8,46.1
CSN1 on BOTTOM "BOTTOM125" (solid, pour order 38): 59.521,45.5 cw(c59.521,45.55) 59.485,45.515 59.265,45.735 cw(c59.3,45.771) 59.25,45.771 59.25,45.942 59.081,46.112 cw(c59.116,46.147) 59.073,46.121 58.922,46.372 cw(c59.05,46.45) 58.9,46.45 58.9,48.9 cw(c59.05,48.9) 59.05,49.05 60.9,49.05 cw(c60.9,48.9) 61.05,48.9 61.05,45.55 cw(c61,45.55) 61,45.5
VDD on BOTTOM "BOTTOM126" (solid, pour order 39): 41 vertices, not listed, extent 48.75,26.255 65.85,32.95
DH1_Q on BOTTOM "BOTTOM127" (solid, pour order 40): 22 vertices, not listed, extent 61.85,45.35 64.375,48.4
DH1 on BOTTOM "BOTTOM128" (solid, pour order 41): 67.371,47.8 cw(c67.371,47.85) 67.335,47.815 67.265,47.885 cw(c67.3,47.921) 67.25,47.921 67.25,48.3 cw(c67.3,48.3) 67.3,48.35 67.9,48.35 cw(c67.9,48.3) 67.95,48.3 67.95,47.921 cw(c67.9,47.921) 67.935,47.885 67.865,47.815 cw(c67.829,47.85) 67.829,47.8
SIG214 on BOTTOM "BOTTOM129" (solid, pour order 42): 17 vertices, not listed, extent 46.75,42.35 49.95,46.6
SIG431 on BOTTOM "BOTTOM130" (solid, pour order 43): 20 vertices, not listed, extent 46.75,39.1 52.35,44
SIG434 on BOTTOM "BOTTOM131" (solid, pour order 44): 25 vertices, not listed, extent 48.6,40.45 52,42.9
SIG431 on BOTTOM "BOTTOM132" (solid, pour order 45): 19 vertices, not listed, extent 50.6,39.25 52.4,41
SIG401 on BOTTOM "BOTTOM133" (solid, pour order 46): 52,37.35 cw(c52,37.4) 51.95,37.4 51.95,37.95 51.815,38.085 cw(c51.85,38.121) 51.8,38.121 51.8,38.65 cw(c51.85,38.65) 51.85,38.7 52.35,38.7 cw(c52.35,38.65) 52.4,38.65 52.4,38.071 cw(c52.35,38.071) 52.385,38.035 52.3,37.95 52.3,37.4 cw(c52.25,37.4) 52.25,37.35
VIN2 on BOTTOM "BOTTOM134" (solid, pour order 47): 31 vertices, not listed, extent 40.726,26.7 51,46.074
SIG431 on BOTTOM "BOTTOM135" (solid, pour order 48): 17 vertices, not listed, extent 47.75,46.9 49.15,48.25
CSP1 on BOTTOM "BOTTOM136" (solid, pour order 49): 49.9,43.75 cw(c49.9,43.8) 49.85,43.8 49.85,49.679 cw(c49.9,49.679) 49.865,49.715 50.485,50.335 cw(c50.521,50.3) 50.521,50.35 57.3,50.35 cw(c57.3,50.2) 57.45,50.2 57.45,46.212 cw(c57.3,46.212) 57.406,46.106 55.065,43.765 cw(c55.029,43.8) 55.029,43.75
no net on Top Solder "TOPSOLDER137" (solid, pour order 0): 21.5,56.5 ccw(c23.5,56.5) 25.5,56.5 ccw(c23.5,56.5)
no net on Top Solder "TOPSOLDER138" (solid, pour order 0): 21.5,23.5 ccw(c23.5,23.5) 25.5,23.5 ccw(c23.5,23.5)
no net on Top Solder "TOPSOLDER139" (solid, pour order 0): 104.5,23.5 ccw(c106.5,23.5) 108.5,23.5 ccw(c106.5,23.5)
no net on Top Solder "TOPSOLDER140" (solid, pour order 0): 104.5,56.5 ccw(c106.5,56.5) 108.5,56.5 ccw(c106.5,56.5)
no net on Top Solder "TOPSOLDER141" (solid, pour order 0): 75.65,42.15 cw(c75.5,42.15) 75.5,42 75.1,42 cw(c75.1,42.15) 74.95,42.15 74.95,42.3 cw(c75.1,42.3) 75.1,42.45 75.5,42.45 cw(c75.5,42.3) 75.65,42.3
no net on Top Solder "TOPSOLDER142" (solid, pour order 0): 58.6,45.35 58.6,45.15 58.3,45.15 58.3,45.35
no net on Bottom Solder "BOTTOMSOLDER143" (solid, pour order 0): 104.5,56.5 ccw(c106.5,56.5) 108.5,56.5 ccw(c106.5,56.5)
no net on Bottom Solder "BOTTOMSOLDER144" (solid, pour order 0): 104.5,23.5 ccw(c106.5,23.5) 108.5,23.5 ccw(c106.5,23.5)
no net on Bottom Solder "BOTTOMSOLDER145" (solid, pour order 0): 21.5,56.5 ccw(c23.5,56.5) 25.5,56.5 ccw(c23.5,56.5)
no net on Bottom Solder "BOTTOMSOLDER146" (solid, pour order 0): 21.5,23.5 ccw(c23.5,23.5) 25.5,23.5 ccw(c23.5,23.5)
no net on Top Overlay "TOPOVERLAY147" (solid, pour order 0): 47.55,35.8 cw(c47.75,35.8) 47.75,36 51.65,36 cw(c51.65,35.8) 51.85,35.8 51.85,33.5 cw(c51.65,33.5) 51.65,33.3 47.75,33.3 cw(c47.75,33.5) 47.55,33.5
no net on Top Overlay "TOPOVERLAY148" (solid, pour order 0): 75.2,47.95 75.2,48.6 75.85,48.3
no net on Top Overlay "TOPOVERLAY149" (solid, pour order 0): 67.2,44.75 67.2,44.1 66.55,44.4
no net on Top Overlay "TOPOVERLAY150" (solid, pour order 0): 37.297,57.174 cw(c37.303,57.172) 37.303,57.179 37.365,57.18 37.455,57.182 37.617,57.182 37.934,57.182 37.934,54.932 37.297,54.935 37.295,56.051 37.295,56.479 37.295,56.841 37.295,57.167 cw(c37.315,57.167) 37.297,57.174
no net on Top Overlay "TOPOVERLAY151" (solid, pour order 0): 27.628,57.182 29.638,57.182 29.638,56.62 28.972,56.62 28.969,54.935 28.3,54.932 28.3,56.62 27.628,56.62
no net on Top Overlay "TOPOVERLAY152" (solid, pour order 0): 127 vertices, not listed, extent 32.354,54.897 34.313,57.218
no net on Top Overlay "TOPOVERLAY153" (solid, pour order 0): 32 vertices, not listed, extent 40.602,54.932 42.898,57.182
no net on Top Overlay "TOPOVERLAY154" (solid, pour order 0): 34.733,57.182 35.367,57.182 35.367,56.361 36.104,56.361 36.104,57.182 36.738,57.182 36.738,54.932 36.104,54.932 36.104,55.798 35.367,55.798 35.367,54.932 34.733,54.932
no net on Top Overlay "TOPOVERLAY155" (solid, pour order 0): 55 vertices, not listed, extent 38.497,54.935 40.432,57.181
no net on Top Overlay "TOPOVERLAY156" (solid, pour order 0): 45 vertices, not listed, extent 29.858,54.895 31.985,57.218
no net on Top Overlay "TOPOVERLAY157" (solid, pour order 0): 58.8,45.85 58.8,46.5 59.024,46.396 ccw(c59.3,46.7) 59.248,46.293 59.398,46.224 ccw(c59.65,45.9) 59.305,46.122
no net on Top Overlay "TOPOVERLAY158" (solid, pour order 0): 73.95,42.05 74.012,42.185 ccw(c73.75,42.5) 74.16,42.505 74.226,42.648 ccw(c74.55,42.9) 74.328,42.555 74.54,42.161 ccw(c74.95,42.15) 74.552,42.05

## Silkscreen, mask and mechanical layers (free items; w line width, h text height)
Top Overlay:
  lines w0.2: 58.5,37 60.9,37 60.9,36.845 60.9,37.7 61.5,38.3 61.5,40.6 ; 60.9,36.9 60.9,37.2 ; 61.3,36.717 61.3,37 64,37 ; 64,36.8 64,37 ; 64.113,38.013 64,37.9 64,37 ; 64.287,38.187 65.5,39.4 65.5,39.9 65.9,40.3 ; 64.6,40.7 64.6,40.3 67.042,40.3 ; 65.4,29.6 66.7,29.6 67.1,30 67.1,30.7 67.216,30.816 ; 65.4,30.7 65.7,30.7 66,31 66.9,31.9 68.8,31.9 69.1,31.6 69.3,31.6 ; 67.558,40.3 68.2,40.3 69,41.1 ; 67.606,31 68.6,31 ; 72.8,25.5 72.8,25.8 72.9,25.9 ; 72.9,28.1 72.9,25.9 ; 76.41,24.49 75.7,25.2 75.7,25.9 72.9,25.9 ; 76.489,24.411 76.5,24.4 ; 76.6,55.5 76.6,52.3 77,52.3 ; 76.728,39.7 77,39.7 ; 76.8,52.3 85.5,52.3 ; 77.1,40.142 77.1,39.1 77.259,38.941 ; 77.1,40.658 77.1,40.892 ; 77.179,41.079 77.4,41.3 78.8,41.3 78.8,41.9 ; 77.6,38.318 77.6,37.3 77.69,37.21 ; 79.1,46.2 79.3,46 79.3,45.6 81.079,45.6 ; 81.421,45.6 81.979,45.6 ; 82.321,45.6 82.879,45.6 ; 83.221,45.6 83.779,45.6 ; 84.121,45.6 84.679,45.6 ; 84.4,45.7 84.4,46.1 ; 84.4,46 84.4,52.3 ; 85.021,45.6 85.579,45.6 ; 85.921,45.6 86.479,45.6 ; 86.821,45.6 87.379,45.6 ; 87.721,45.6 88.6,45.6 ; 89.813,22.287 90.15,21.95
  text "OUTPUT" at 99.8,52.45 h0.71
  text "INPUT" at 21.438,51.435 h0.8
  text "BUCK-BOOST" at 40.2,36.1 h0.89
  text "TYPE3" at 40.2,34.45 h0.71
  text "CONTROL" at 61.227,24.244 h0.8
  text "INPUT" at 61.189,22.835 h0.8
Bottom Overlay:
  lines w0.2: 53.4,51 53.4,51.35 ; 53.4,51.1 53.4,50.45 57.85,50.45 ; 57.75,50.4 57.75,48.45 57.75,46.45 57.95,46.25 ; 57.8,50.45 58.45,50.45 58.45,51.35 ; 59.1,50.15 59.1,49.75 65.6,49.75 65.6,50.25 ; 60.95,49.8 60.95,45.25 62.45,43.75 ; 61.35,46.65 61.35,48.9 63.5,48.9 66.65,48.9 ; 62.4,41.5 62.4,43.2 ; 62.4,43.15 62.4,43.6 62.5,43.7 65.479,43.7 ; 64.85,54.25 65.65,54.25 65.65,57.15 65.338,57.15 ; 65.75,55.65 66.65,55.65 66.65,49.05 ; 65.821,43.7 66.084,43.7 ; 66.6,48.95 66.6,49.8 ; 66.7,48.9 68.7,48.9 68.7,48.6 ; 66.716,43.7 67.2,43.7 67.2,43.35 ; 68,53 68,52.2 69.8,52.2 ; 68.9,46.7 68.9,47.8 70.9,47.8 70.9,47.1 ; 69.85,47.85 69.85,52.2 71.1,52.2 71.1,53 ; 71.15,46.25 71.15,47.4 73.9,47.4 73.9,46.75 74.169,46.481 ; 72.1,52.618 72.1,52.2 75.3,52.2 75.3,52.7 75.3,53 ; 73.7,47.5 73.7,49.95 ; 73.7,49.8 73.7,52.2 ; 74.481,46.169 75.3,45.35 75.3,45 ; 75.1,30.929 75.1,26.8 78.8,26.8 ; 75.1,31.271 75.1,31.7 ; 75.135,31.1 77.4,31.1 77.4,32.1 ; 76.6,51.05 76.6,50.2 81.85,50.2 81.85,52.15 ; 77.8,33.6 77.8,33.2 ; 77.8,38.3 77.9,38.3 ; 77.8,39.3 77.8,39.7 81.7,39.7 81.7,39.2 81.7,38.3 81.1,38.3 ; 78.8,28.1 77.8,28.1 77.8,33.2 ; 80,38.3 81,38.3 ; 80.1,48.3 80.1,50.15 ; 81.7,33.8 81.7,33.2 77.8,33.2 ; 81.7,39.5 81.7,39.9 ; 81.7,39.8 81.7,40.6 ; 82.2,34.7 81.8,35.1 ; 82.2,35.5 81.8,35.1 ; 83,35.1 81.8,35.1 ; 84,29.9 83.1,29.9 83.1,39.3 83.8,39.3 91,39.3
  text "ADDR SELECT" at 84.9,40.7 h0.43
  text "CURRENT COMP" at 85.885,27.3 h0.43
  text "VOLTAGE COMP" at 85.885,26.1 h0.43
